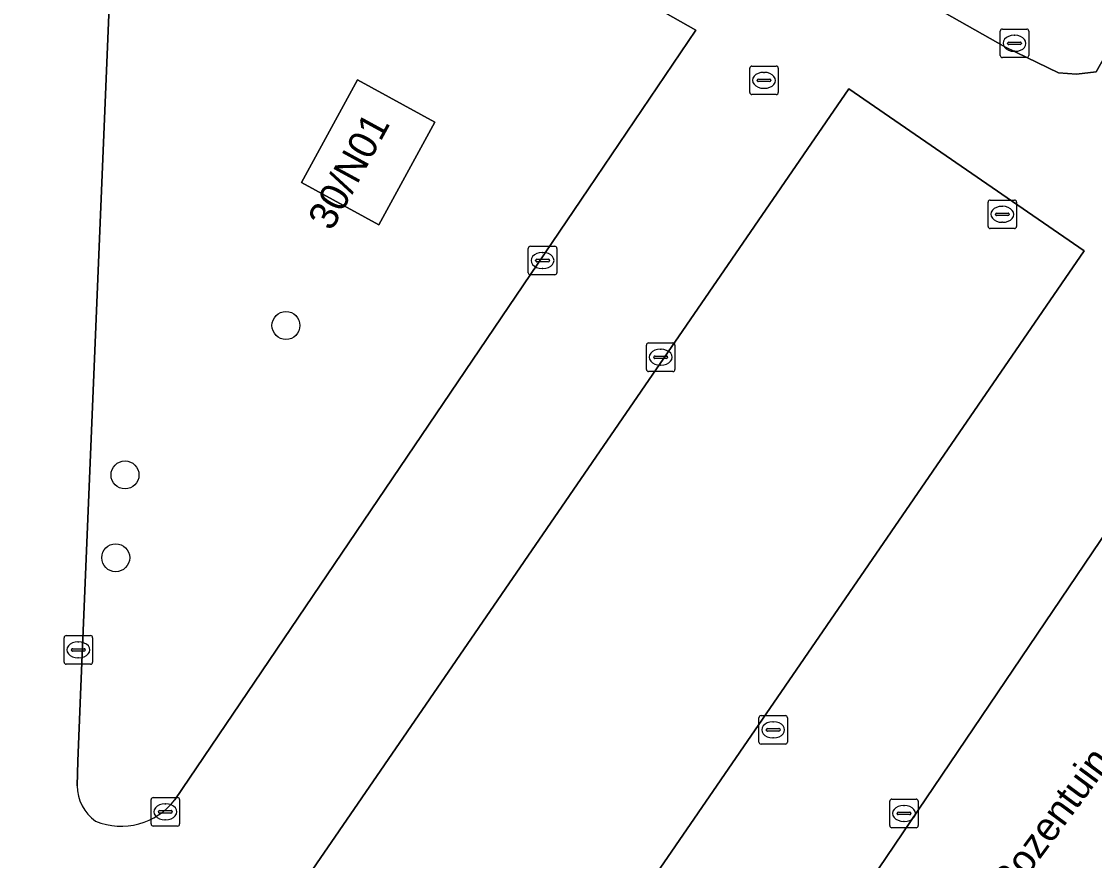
# Model space of a CAD drawing. Extents: x 161798 to 162385, y 382315 to 382833.
# Drawn here: x 161900.62 to 161938.21, y 382750.85 to 382780.22 of the extents above; entities that cross this region are included whole.
import ezdxf

# ---------------------------------------------------------------- set-up
doc = ezdxf.new("R2010")
doc.units = 0
for name, color, linetype in [('IMGEO_Boom', 7, 'Continuous'), ('IMGEO_Kolk', 7, 'Continuous'), ('IMGEO_Openbare_ruimte_label', 7, 'Continuous'), ('IMGEO_Pand', 7, 'Continuous'), ('IMGEO_Pand_nummerreeks', 7, 'Continuous'), ('IMGEO_Parkeervlak_open', 7, 'Continuous'), ('IMGEO_Rijbaan_lokaal_open', 7, 'Continuous'), ('IMGEO_Rioolput', 7, 'Continuous')]:
    doc.layers.add(name, color=color, linetype=linetype)

msp = doc.modelspace()

# ---------------------------------------------------------------- linework, layer by layer
at = {"layer": 'IMGEO_Boom'}
for centre in [(161909.881, 382769.575), (161904.244, 382764.345), (161903.919, 382761.445)]:
    msp.add_circle(centre, 0.489, dxfattribs=at)
at = {"layer": 'IMGEO_Kolk'}
for p, q in [((161934.902, 382779.027), (161934.902, 382779.879)), ((161934.977, 382779.953), (161935.829, 382779.953)), ((161935.903, 382779.879), (161935.903, 382779.027)), ((161935.161, 382779.447), (161935.161, 382779.459)), ((161935.599, 382779.41), (161935.201, 382779.41)), ((161935.204, 382779.496), (161935.602, 382779.496)), ((161935.39, 382779.733), (161935.415, 382779.733)), ((161935.645, 382779.459), (161935.645, 382779.447)), ((161935.413, 382779.173), (161935.388, 382779.173)), ((161935.829, 382778.953), (161934.977, 382778.953)), ((161934.475, 382773.041), (161934.475, 382773.893)), ((161934.55, 382773.967), (161935.402, 382773.967)), ((161934.963, 382773.747), (161934.988, 382773.747)), ((161935.476, 382773.893), (161935.476, 382773.041)), ((161934.734, 382773.461), (161934.734, 382773.473)), ((161935.172, 382773.424), (161934.774, 382773.424)), ((161934.777, 382773.51), (161935.175, 382773.51)), ((161935.218, 382773.473), (161935.218, 382773.461)), ((161934.986, 382773.187), (161934.961, 382773.187)), ((161935.402, 382772.967), (161934.55, 382772.967)), ((161918.37, 382771.423), (161918.37, 382772.275)), ((161918.445, 382772.349), (161919.297, 382772.349)), ((161919.371, 382772.275), (161919.371, 382771.423)), ((161918.672, 382771.892), (161919.07, 382771.892)), ((161918.858, 382772.129), (161918.883, 382772.129)), ((161918.629, 382771.843), (161918.629, 382771.855)), ((161919.067, 382771.806), (161918.669, 382771.806)), ((161918.881, 382771.569), (161918.856, 382771.569)), ((161919.113, 382771.855), (161919.113, 382771.843)), ((161919.297, 382771.349), (161918.445, 382771.349)), ((161922.508, 382768.038), (161922.508, 382768.89)), ((161922.583, 382768.964), (161923.435, 382768.964)), ((161923.509, 382768.89), (161923.509, 382768.038)), ((161922.81, 382768.507), (161923.208, 382768.507)), ((161922.996, 382768.744), (161923.021, 382768.744)), ((161922.767, 382768.458), (161922.767, 382768.47)), ((161923.205, 382768.421), (161922.807, 382768.421)), ((161923.019, 382768.184), (161922.994, 382768.184)), ((161923.251, 382768.47), (161923.251, 382768.458)), ((161923.435, 382767.964), (161922.583, 382767.964)), ((161926.449, 382754.995), (161926.449, 382755.847)), ((161926.524, 382755.921), (161927.376, 382755.921)), ((161926.937, 382755.701), (161926.962, 382755.701)), ((161927.45, 382755.847), (161927.45, 382754.995)), ((161926.708, 382755.415), (161926.708, 382755.427)), ((161927.146, 382755.378), (161926.748, 382755.378)), ((161926.751, 382755.464), (161927.149, 382755.464)), ((161927.192, 382755.427), (161927.192, 382755.415)), ((161926.96, 382755.141), (161926.935, 382755.141)), ((161927.376, 382754.921), (161926.524, 382754.921)), ((161905.157, 382752.126), (161905.157, 382752.978)), ((161905.232, 382753.052), (161906.084, 382753.052)), ((161905.645, 382752.832), (161905.67, 382752.832)), ((161906.158, 382752.978), (161906.158, 382752.126)), ((161931.031, 382752.07), (161931.031, 382752.922)), ((161931.106, 382752.996), (161931.958, 382752.996)), ((161931.519, 382752.776), (161931.544, 382752.776)), ((161932.032, 382752.922), (161932.032, 382752.07)), ((161905.416, 382752.546), (161905.416, 382752.558)), ((161905.854, 382752.509), (161905.456, 382752.509)), ((161905.459, 382752.595), (161905.857, 382752.595)), ((161905.9, 382752.558), (161905.9, 382752.546)), ((161931.29, 382752.49), (161931.29, 382752.502)), ((161931.728, 382752.453), (161931.33, 382752.453)), ((161931.333, 382752.539), (161931.731, 382752.539)), ((161931.774, 382752.502), (161931.774, 382752.49)), ((161906.084, 382752.052), (161905.232, 382752.052)), ((161905.668, 382752.272), (161905.643, 382752.272)), ((161931.958, 382751.996), (161931.106, 382751.996)), ((161931.542, 382752.216), (161931.517, 382752.216))]:
    msp.add_line(p, q, dxfattribs=at)
for points in [[(161934.902, 382779.027), (161934.902, 382779.879)], [(161934.977, 382779.953), (161935.829, 382779.953)], [(161935.903, 382779.879), (161935.903, 382779.027)], [(161935.829, 382778.953), (161934.977, 382778.953)], [(161934.475, 382773.041), (161934.475, 382773.893)], [(161934.55, 382773.967), (161935.402, 382773.967)], [(161935.476, 382773.893), (161935.476, 382773.041)], [(161935.402, 382772.967), (161934.55, 382772.967)], [(161918.37, 382771.423), (161918.37, 382772.275)], [(161918.445, 382772.349), (161919.297, 382772.349)], [(161919.371, 382772.275), (161919.371, 382771.423)], [(161919.297, 382771.349), (161918.445, 382771.349)], [(161922.508, 382768.038), (161922.508, 382768.89)], [(161922.583, 382768.964), (161923.435, 382768.964)], [(161923.509, 382768.89), (161923.509, 382768.038)], [(161923.435, 382767.964), (161922.583, 382767.964)], [(161926.449, 382754.995), (161926.449, 382755.847)], [(161926.524, 382755.921), (161927.376, 382755.921)], [(161927.45, 382755.847), (161927.45, 382754.995)], [(161927.376, 382754.921), (161926.524, 382754.921)], [(161905.157, 382752.126), (161905.157, 382752.978)], [(161905.232, 382753.052), (161906.084, 382753.052)], [(161906.158, 382752.978), (161906.158, 382752.126)], [(161931.031, 382752.07), (161931.031, 382752.922)], [(161931.106, 382752.996), (161931.958, 382752.996)], [(161932.032, 382752.922), (161932.032, 382752.07)], [(161906.084, 382752.052), (161905.232, 382752.052)], [(161931.958, 382751.996), (161931.106, 382751.996)]]:
    msp.add_lwpolyline(points, dxfattribs=at)
for centre, radius, start, end in [((161934.979, 382779.877), 0.0765, 91.552, 178.448), ((161934.979, 382779.877), 0.0765, 91.552, 178.448), ((161935.827, 382779.877), 0.0765, 1.552, 88.448), ((161935.827, 382779.877), 0.0765, 1.552, 88.448), ((161935.201, 382779.456), 0.0403, 85.8775, 175.7526), ((161935.198, 382779.446), 0.0366, 178.938, 274.7102), ((161935.602, 382779.453), 0.043, 264.8664, 352.4533), ((161935.606, 382779.458), 0.0386, 1.7309, 96.639), ((161934.979, 382779.029), 0.0765, 181.552, 268.448), ((161934.979, 382779.029), 0.0765, 181.552, 268.448), ((161935.827, 382779.029), 0.0765, 271.552, 358.448), ((161935.827, 382779.029), 0.0765, 271.552, 358.448), ((161934.552, 382773.891), 0.0765, 91.552, 178.448), ((161934.552, 382773.891), 0.0765, 91.552, 178.448), ((161935.4, 382773.891), 0.0765, 1.552, 88.448), ((161935.4, 382773.891), 0.0765, 1.552, 88.448), ((161934.774, 382773.47), 0.0403, 85.8775, 175.7526), ((161934.771, 382773.46), 0.0366, 178.938, 274.7102), ((161935.175, 382773.467), 0.043, 264.8664, 352.4533), ((161935.179, 382773.472), 0.0386, 1.7309, 96.639), ((161934.552, 382773.043), 0.0765, 181.552, 268.448), ((161934.552, 382773.043), 0.0765, 181.552, 268.448), ((161935.4, 382773.043), 0.0765, 271.552, 358.448), ((161935.4, 382773.043), 0.0765, 271.552, 358.448), ((161918.447, 382772.273), 0.0765, 91.552, 178.448), ((161918.447, 382772.273), 0.0765, 91.552, 178.448), ((161919.295, 382772.273), 0.0765, 1.552, 88.448), ((161919.295, 382772.273), 0.0765, 1.552, 88.448), ((161918.669, 382771.852), 0.0403, 85.8775, 175.7526), ((161919.074, 382771.854), 0.0386, 1.7309, 96.639), ((161918.666, 382771.842), 0.0366, 178.938, 274.7102), ((161919.07, 382771.849), 0.043, 264.8664, 352.4533), ((161918.447, 382771.425), 0.0765, 181.552, 268.448), ((161918.447, 382771.425), 0.0765, 181.552, 268.448), ((161919.295, 382771.425), 0.0765, 271.552, 358.448), ((161919.295, 382771.425), 0.0765, 271.552, 358.448), ((161922.585, 382768.888), 0.0765, 91.552, 178.448), ((161922.585, 382768.888), 0.0765, 91.552, 178.448), ((161923.433, 382768.888), 0.0765, 1.552, 88.448), ((161923.433, 382768.888), 0.0765, 1.552, 88.448), ((161922.807, 382768.467), 0.0403, 85.8775, 175.7526), ((161923.212, 382768.469), 0.0386, 1.7309, 96.639), ((161922.804, 382768.457), 0.0366, 178.938, 274.7102), ((161923.208, 382768.464), 0.043, 264.8664, 352.4533), ((161922.585, 382768.04), 0.0765, 181.552, 268.448), ((161922.585, 382768.04), 0.0765, 181.552, 268.448), ((161923.433, 382768.04), 0.0765, 271.552, 358.448), ((161923.433, 382768.04), 0.0765, 271.552, 358.448), ((161926.526, 382755.845), 0.0765, 91.552, 178.448), ((161926.526, 382755.845), 0.0765, 91.552, 178.448), ((161927.374, 382755.845), 0.0765, 1.552, 88.448), ((161927.374, 382755.845), 0.0765, 1.552, 88.448), ((161926.748, 382755.424), 0.0403, 85.8775, 175.7526), ((161926.745, 382755.414), 0.0366, 178.938, 274.7102), ((161927.149, 382755.421), 0.043, 264.8664, 352.4533), ((161927.153, 382755.426), 0.0386, 1.7309, 96.639), ((161926.526, 382754.997), 0.0765, 181.552, 268.448), ((161926.526, 382754.997), 0.0765, 181.552, 268.448), ((161927.374, 382754.997), 0.0765, 271.552, 358.448), ((161927.374, 382754.997), 0.0765, 271.552, 358.448), ((161905.234, 382752.976), 0.0765, 91.552, 178.448), ((161905.234, 382752.976), 0.0765, 91.552, 178.448), ((161906.082, 382752.976), 0.0765, 1.552, 88.448), ((161906.082, 382752.976), 0.0765, 1.552, 88.448), ((161931.108, 382752.92), 0.0765, 91.552, 178.448), ((161931.108, 382752.92), 0.0765, 91.552, 178.448), ((161931.956, 382752.92), 0.0765, 1.552, 88.448), ((161931.956, 382752.92), 0.0765, 1.552, 88.448), ((161905.456, 382752.555), 0.0403, 85.8775, 175.7526), ((161905.453, 382752.545), 0.0366, 178.938, 274.7102), ((161905.857, 382752.552), 0.043, 264.8664, 352.4533), ((161905.861, 382752.557), 0.0386, 1.7309, 96.639), ((161931.33, 382752.499), 0.0403, 85.8775, 175.7526), ((161931.327, 382752.489), 0.0366, 178.938, 274.7102), ((161931.731, 382752.496), 0.043, 264.8664, 352.4533), ((161931.735, 382752.501), 0.0386, 1.7309, 96.639), ((161905.234, 382752.128), 0.0765, 181.552, 268.448), ((161905.234, 382752.128), 0.0765, 181.552, 268.448), ((161906.082, 382752.128), 0.0765, 271.552, 358.448), ((161906.082, 382752.128), 0.0765, 271.552, 358.448), ((161931.108, 382752.072), 0.0765, 181.552, 268.448), ((161931.108, 382752.072), 0.0765, 181.552, 268.448), ((161931.956, 382752.072), 0.0765, 271.552, 358.448), ((161931.956, 382752.072), 0.0765, 271.552, 358.448)]:
    msp.add_arc(centre, radius, start, end, dxfattribs=at)
for centre, major_axis, ratio, start_param, end_param in [((161935.389, 382779.453), (-0.387, 0.002), 0.722429, 4.712389, 7.853982), ((161935.414, 382779.453), (-0.39, 0.002), 0.717154, 1.570796, 4.712389), ((161934.962, 382773.467), (-0.387, 0.002), 0.722429, 4.712389, 7.853982), ((161934.987, 382773.467), (-0.39, 0.002), 0.717154, 1.570796, 4.712389), ((161918.857, 382771.849), (-0.387, 0.002), 0.722429, 4.712389, 7.853982), ((161918.882, 382771.849), (-0.39, 0.002), 0.717154, 1.570796, 4.712389), ((161922.995, 382768.464), (-0.387, 0.002), 0.722429, 4.712389, 7.853982), ((161923.02, 382768.464), (-0.39, 0.002), 0.717154, 1.570796, 4.712389), ((161926.936, 382755.421), (-0.387, 0.002), 0.722429, 4.712389, 7.853982), ((161926.961, 382755.421), (-0.39, 0.002), 0.717154, 1.570796, 4.712389), ((161905.644, 382752.552), (-0.387, 0.002), 0.722429, 4.712389, 7.853982), ((161905.669, 382752.552), (-0.39, 0.002), 0.717154, 1.570796, 4.712389), ((161931.518, 382752.496), (-0.387, 0.002), 0.722429, 4.712389, 7.853982), ((161931.543, 382752.496), (-0.39, 0.002), 0.717154, 1.570796, 4.712389)]:
    msp.add_ellipse(centre, major_axis=major_axis, ratio=ratio, start_param=start_param, end_param=end_param, dxfattribs=at)
at = {"layer": 'IMGEO_Pand'}
msp.add_lwpolyline([(161913.135, 382773.099), (161915.099, 382776.688), (161912.385, 382778.173), (161910.421, 382774.585)], close=True, dxfattribs=at)
at = {"layer": 'IMGEO_Parkeervlak_open'}
for points in [[(161905.86, 382803.349), (161908.702, 382808.365), (161908.257, 382808.617), (161908.132, 382808.688), (161906.643, 382807.812), (161902.403, 382808.653), (161902.633, 382809.817), (161893.778, 382811.571), (161893.618, 382811.603), (161893.112, 382809.049), (161891.134, 382799.077), (161891.132, 382799.067), (161902.076, 382798.594), (161902.137, 382797.939), (161935.082, 382779.315), (161936.947, 382778.425), (161937.569, 382778.374), (161938.258, 382778.46), (161941.059, 382783.403)], [(161910.421, 382774.585), (161912.385, 382778.173), (161915.099, 382776.688), (161913.135, 382773.099)]]:
    msp.add_lwpolyline(points, close=True, dxfattribs=at)
for points in [[(161905.705, 382790.387), (161903.009, 382785.406), (161903.87, 382784.955), (161902.683, 382756.65), (161902.586, 382754.321), (161902.568, 382753.466)], [(161905.992, 382752.968), (161920.477, 382774.363), (161924.235, 382779.914), (161905.705, 382790.387)], [(161929.946, 382734.127), (161941.685, 382750), (161954.083, 382766.765), (161967.663, 382756.723), (161969.821, 382755.127), (161971.541, 382753.922), (161973.752, 382757.022), (161969.677, 382760.169), (161968.421, 382761.136), (161964.431, 382764.206), (161969.61, 382770.941), (161968.864, 382771.513), (161950.654, 382785.52), (161946.102, 382779.602), (161945.706, 382772.813), (161945.633, 382772.713), (161923.425, 382739.892), (161911.109, 382723.212), (161905.87, 382718.099), (161905.781, 382717.991)], [(161937.838, 382772.19), (161929.595, 382777.856), (161901.164, 382736.49), (161900.744, 382726.165)], [(161904.416, 382724.961), (161907.751, 382728.414), (161937.838, 382772.19)]]:
    msp.add_lwpolyline(points, dxfattribs=at)
for centre, radius, start, end in [((161904.085, 382753.466), 1.517, 179.997, 234.9983), ((161904.111, 382754.431), 2.383, 247.909, 322.1258)]:
    msp.add_arc(centre, radius, start, end, dxfattribs=at)
at = {"layer": 'IMGEO_Rijbaan_lokaal_open'}
for points in [[(161961.207, 382794.293), (161957.244, 382796.796), (161956.77, 382795.96), (161954.636, 382792.49), (161954.251, 382791.811), (161951.44, 382786.77), (161950.985, 382785.967), (161950.005, 382786.522), (161944.77, 382789.518), (161944.584, 382789.623), (161941.059, 382783.403), (161938.258, 382778.46), (161937.569, 382778.374), (161936.947, 382778.425), (161935.082, 382779.315), (161902.137, 382797.939), (161902.076, 382798.594), (161891.132, 382799.067), (161890.892, 382797.855), (161890.86, 382797.691), (161893.398, 382797.189), (161893.549, 382797.139), (161893.585, 382797.678), (161898.337, 382796.75)], [(161902.568, 382753.466), (161902.586, 382754.321), (161902.683, 382756.65), (161903.87, 382784.955), (161903.009, 382785.406), (161905.705, 382790.387), (161924.235, 382779.914), (161920.477, 382774.363)], [(161905.781, 382717.991), (161905.87, 382718.099), (161911.109, 382723.212), (161923.425, 382739.892), (161945.633, 382772.713), (161945.706, 382772.813), (161946.102, 382779.602)], [(161900.744, 382726.165), (161901.164, 382736.49), (161929.595, 382777.856)], [(161929.595, 382777.856), (161937.838, 382772.19), (161907.751, 382728.414), (161904.416, 382724.961)], [(161920.477, 382774.363), (161905.992, 382752.968)]]:
    msp.add_lwpolyline(points, dxfattribs=at)
for centre, radius, start, end in [((161904.085, 382753.466), 1.517, 179.997, 234.9983), ((161904.111, 382754.431), 2.383, 247.909, 322.1258)]:
    msp.add_arc(centre, radius, start, end, dxfattribs=at)
at = {"layer": 'IMGEO_Rioolput'}
for p, q in [((161926.202, 382778.657), (161927.054, 382778.657)), ((161926.127, 382777.731), (161926.127, 382778.583)), ((161926.615, 382778.437), (161926.64, 382778.437)), ((161927.128, 382778.583), (161927.128, 382777.731)), ((161926.386, 382778.151), (161926.386, 382778.163)), ((161926.824, 382778.114), (161926.426, 382778.114)), ((161926.429, 382778.2), (161926.827, 382778.2)), ((161926.638, 382777.877), (161926.613, 382777.877)), ((161926.87, 382778.163), (161926.87, 382778.151)), ((161927.054, 382777.657), (161926.202, 382777.657)), ((161902.184, 382758.718), (161903.036, 382758.718)), ((161902.109, 382757.792), (161902.109, 382758.644)), ((161902.597, 382758.498), (161902.622, 382758.498)), ((161903.11, 382758.644), (161903.11, 382757.792)), ((161902.368, 382758.212), (161902.368, 382758.224)), ((161902.806, 382758.175), (161902.408, 382758.175)), ((161902.411, 382758.261), (161902.809, 382758.261)), ((161902.852, 382758.224), (161902.852, 382758.212)), ((161903.036, 382757.718), (161902.184, 382757.718)), ((161902.62, 382757.938), (161902.595, 382757.938))]:
    msp.add_line(p, q, dxfattribs=at)
for points in [[(161926.202, 382778.657), (161927.054, 382778.657)], [(161926.127, 382777.731), (161926.127, 382778.583)], [(161927.128, 382778.583), (161927.128, 382777.731)], [(161927.054, 382777.657), (161926.202, 382777.657)], [(161902.184, 382758.718), (161903.036, 382758.718)], [(161902.109, 382757.792), (161902.109, 382758.644)], [(161903.11, 382758.644), (161903.11, 382757.792)], [(161903.036, 382757.718), (161902.184, 382757.718)]]:
    msp.add_lwpolyline(points, dxfattribs=at)
for centre, radius, start, end in [((161926.204, 382778.581), 0.0765, 91.552, 178.448), ((161926.204, 382778.581), 0.0765, 91.552, 178.448), ((161927.052, 382778.581), 0.0765, 1.552, 88.448), ((161927.052, 382778.581), 0.0765, 1.552, 88.448), ((161926.426, 382778.16), 0.0403, 85.8775, 175.7526), ((161926.423, 382778.15), 0.0366, 178.938, 274.7102), ((161926.827, 382778.157), 0.043, 264.8664, 352.4533), ((161926.831, 382778.162), 0.0386, 1.7309, 96.639), ((161926.204, 382777.733), 0.0765, 181.552, 268.448), ((161926.204, 382777.733), 0.0765, 181.552, 268.448), ((161927.052, 382777.733), 0.0765, 271.552, 358.448), ((161927.052, 382777.733), 0.0765, 271.552, 358.448), ((161902.186, 382758.642), 0.0765, 91.552, 178.448), ((161902.186, 382758.642), 0.0765, 91.552, 178.448), ((161903.034, 382758.642), 0.0765, 1.552, 88.448), ((161903.034, 382758.642), 0.0765, 1.552, 88.448), ((161902.408, 382758.221), 0.0403, 85.8775, 175.7526), ((161902.405, 382758.211), 0.0366, 178.938, 274.7102), ((161902.809, 382758.218), 0.043, 264.8664, 352.4533), ((161902.813, 382758.223), 0.0386, 1.7309, 96.639), ((161902.186, 382757.794), 0.0765, 181.552, 268.448), ((161902.186, 382757.794), 0.0765, 181.552, 268.448), ((161903.034, 382757.794), 0.0765, 271.552, 358.448), ((161903.034, 382757.794), 0.0765, 271.552, 358.448)]:
    msp.add_arc(centre, radius, start, end, dxfattribs=at)
for centre, major_axis, ratio, start_param, end_param in [((161926.614, 382778.157), (-0.387, 0.002), 0.722429, 4.712389, 7.853982), ((161926.639, 382778.157), (-0.39, 0.002), 0.717154, 1.570796, 4.712389), ((161902.596, 382758.218), (-0.387, 0.002), 0.722429, 4.712389, 7.853982), ((161902.621, 382758.218), (-0.39, 0.002), 0.717154, 1.570796, 4.712389)]:
    msp.add_ellipse(centre, major_axis=major_axis, ratio=ratio, start_param=start_param, end_param=end_param, dxfattribs=at)

# ---------------------------------------------------------------- texts
at = {"layer": 'IMGEO_Openbare_ruimte_label'}
msp.add_text('De Rozentuin', height=1, rotation=53.4967, dxfattribs=at).set_placement((161934.021, 382747.812))
at = {"layer": 'IMGEO_Pand_nummerreeks'}
msp.add_text('30/N01', height=1, rotation=61.403, dxfattribs=at).set_placement((161911.483, 382772.851))

doc.saveas('drawing.dxf')
